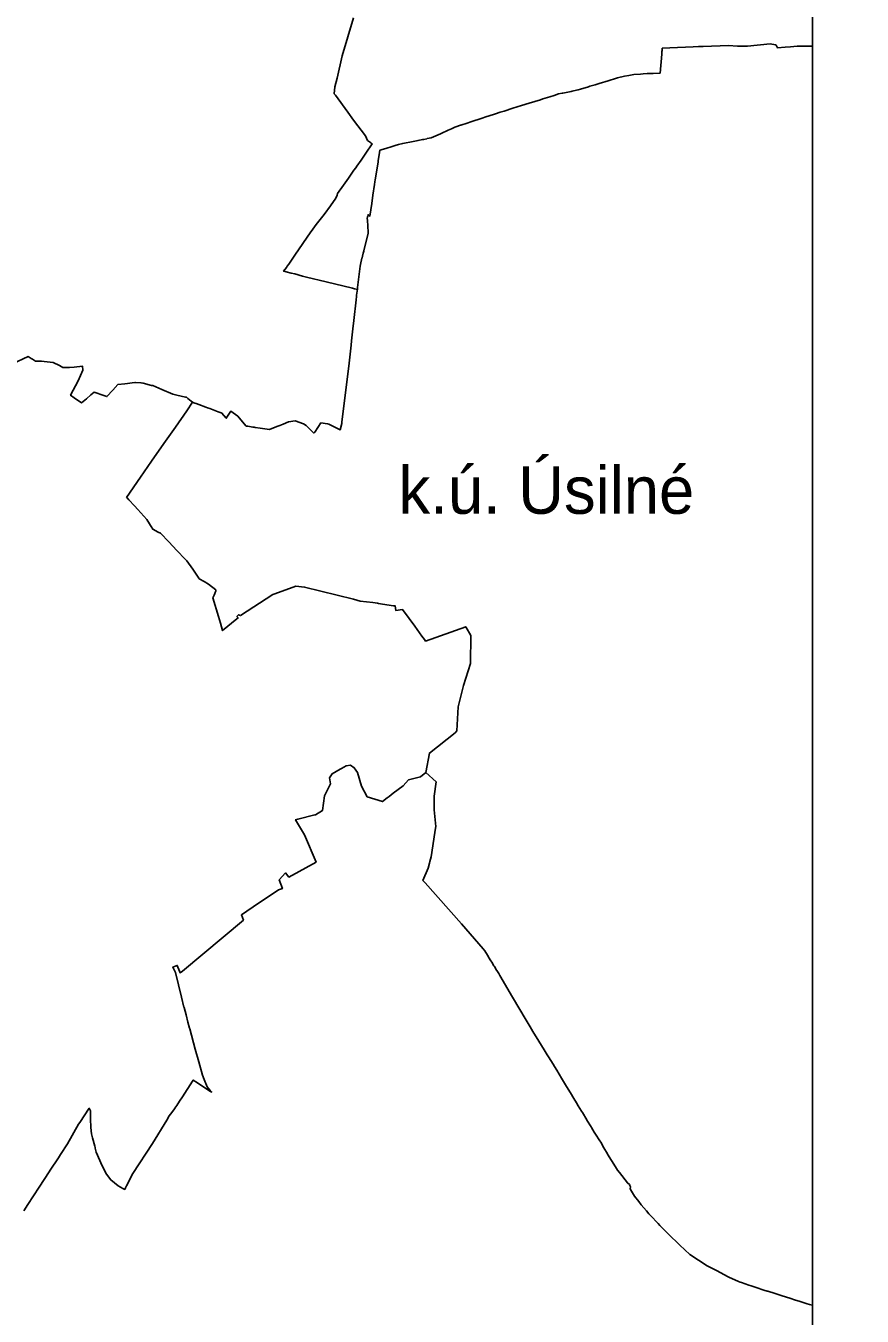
# Model space of a CAD drawing. Extents: x -757891 to -747391, y -1166581 to -1159156.
# Drawn here: x -754302 to -752536, y -1164084 to -1161361 of the extents above; entities that cross this region are included whole.
import ezdxf

# ---------------------------------------------------------------- set-up
doc = ezdxf.new("R2010")
doc.units = 0
for name, color, linetype in [('formát', 7, 'Continuous'), ('Hranice katastrálního území_bez dotčení', 7, 'Continuous'), ('Hranice katastrálního území_dotčené', 7, 'Continuous')]:
    doc.layers.add(name, color=color, linetype=linetype)

msp = doc.modelspace()

# ---------------------------------------------------------------- linework, layer by layer
at = {"layer": 'formát'}
for points in [[(-757891.5, -1159156.4), (-752641.5, -1159156.4), (-752641.5, -1166581.4), (-757891.5, -1166581.4)], [(-752641.5, -1159156.4), (-747391.5, -1159156.4), (-747391.5, -1166581.4), (-752641.5, -1166581.4)]]:
    msp.add_lwpolyline(points, close=True, dxfattribs=at)
at = {"layer": 'Hranice katastrálního území_bez dotčení'}
for points in [[(-753542, -1161619.2), (-753529.1, -1161615.2), (-753522.6, -1161613.2), (-753515.2, -1161611.2), (-753506.6, -1161608.8), (-753484.3, -1161604.5), (-753474.2, -1161602.5), (-753464.5, -1161600.7), (-753462.1, -1161600.2), (-753455.6, -1161598.7), (-753455.2, -1161598.6), (-753446.1, -1161596.6), (-753426.7, -1161588.5), (-753425.5, -1161587.9), (-753410.2, -1161580.9), (-753403.5, -1161577.9), (-753396.3, -1161574.6), (-753394.1, -1161573.9), (-753384.3, -1161570.5), (-753384, -1161570.4), (-753370.5, -1161565.8), (-753362.8, -1161563.3), (-753338.7, -1161555.5), (-753330.8, -1161552.9), (-753314.8, -1161547.7), (-753310.8, -1161546.4), (-753300.6, -1161543.1), (-753292, -1161540.4), (-753274.1, -1161534.6), (-753255.6, -1161528.7), (-753239.3, -1161523.7), (-753215.4, -1161516.4), (-753210.4, -1161514.9), (-753201.1, -1161511.9), (-753195.8, -1161510.2), (-753187.1, -1161507.4), (-753177.3, -1161504.3), (-753169.8, -1161502.8), (-753168.8, -1161502.6), (-753150.8, -1161498.9), (-753148.8, -1161498.5), (-753139.7, -1161496.6), (-753136.2, -1161495.6), (-753135.8, -1161495.4), (-753131.3, -1161494.1), (-753114.5, -1161489), (-753111.8, -1161488.2), (-753100.5, -1161484.8), (-753092, -1161482.2), (-753072.9, -1161476.5), (-753055.4, -1161471.2), (-753053, -1161470.6), (-753038.4, -1161467), (-753029.1, -1161465.4), (-753018.5, -1161463.6), (-753004.8, -1161462.3), (-752998.8, -1161461.8), (-752990.2, -1161461.4), (-752981.6, -1161461.1), (-752979.7, -1161461), (-752977.8, -1161461), (-752963.2, -1161460.4), (-752959.7, -1161420.1), (-752959.2, -1161415.1), (-752959.2, -1161414.7), (-752959, -1161412.5), (-752958.6, -1161408), (-752942.6, -1161407.1), (-752893.5, -1161405), (-752881.8, -1161404.5), (-752872.1, -1161404.2), (-752818.6, -1161402.3), (-752799.9, -1161403.4), (-752778.8, -1161403.5), (-752730.7, -1161398.9), (-752719.6, -1161400.9), (-752718.1, -1161401.1), (-752715.3, -1161406.8), (-752699.4, -1161405.5), (-752688, -1161404.6), (-752673.7, -1161403.5), (-752655.6, -1161403.4), (-752641.5, -1161403.3)], [(-753602.1, -1161917), (-753601.7, -1161913), (-753596.6, -1161867.6), (-753595.9, -1161864.3), (-753592.6, -1161850.7), (-753592.3, -1161849.8), (-753591.6, -1161846.8), (-753589.9, -1161840), (-753588.9, -1161835.9), (-753588.7, -1161835.2), (-753579.6, -1161798.2), (-753579.2, -1161796), (-753580.9, -1161770.5), (-753581.4, -1161767.4), (-753580.6, -1161763.9), (-753580.2, -1161762.3), (-753579.5, -1161759.3), (-753575.8, -1161762.1), (-753571.9, -1161735.4), (-753569.3, -1161717.7), (-753566, -1161695.7), (-753565.4, -1161690.1), (-753564.8, -1161685.6), (-753562.3, -1161673.4), (-753558.5, -1161647.5), (-753558.1, -1161645), (-753556.2, -1161632.9), (-753554.8, -1161623.2), (-753542, -1161619.2)], [(-753129, -1163650.8), (-753135.8, -1163639.4), (-753139.7, -1163633.1), (-753144.9, -1163624.4), (-753152.5, -1163611.9), (-753153.8, -1163609.8), (-753162.7, -1163595), (-753171.2, -1163580.9), (-753181.3, -1163564.3), (-753186.1, -1163556.6), (-753189.2, -1163551.6), (-753198.8, -1163536.1), (-753201.3, -1163532.1), (-753208, -1163521.4), (-753219.2, -1163503.3), (-753232.1, -1163482.5), (-753237.5, -1163473.1), (-753239.8, -1163469.1), (-753245.7, -1163459), (-753274.4, -1163410), (-753301.3, -1163364.9), (-753303.9, -1163360.6), (-753307.7, -1163354.3), (-753308.3, -1163353.2), (-753312.9, -1163345.7), (-753314, -1163344), (-753318.7, -1163336.2), (-753320.3, -1163333.6), (-753325.1, -1163325.7), (-753326.1, -1163324), (-753330.8, -1163316.3), (-753333, -1163312.8), (-753336.8, -1163308.4), (-753354.8, -1163287.4), (-753382.1, -1163255.6), (-753459.3, -1163168.8), (-753461.2, -1163166.6), (-753462.1, -1163165.9), (-753463.8, -1163163.9), (-753452.8, -1163138.1), (-753450, -1163127.2), (-753449.2, -1163124.1), (-753446.5, -1163113.9), (-753445.1, -1163105), (-753437.9, -1163058.1), (-753436.7, -1163050.2), (-753439.9, -1163014.7), (-753440.4, -1162986.2), (-753436.2, -1162955.7), (-753457.6, -1162935.9)], [(-752641.5, -1164060.6), (-752642.2, -1164060.4), (-752648, -1164058.5), (-752652.4, -1164057.2), (-752665.1, -1164053.3), (-752667.4, -1164052.6), (-752679.2, -1164048.9), (-752687.4, -1164046.3), (-752707.6, -1164039.8), (-752720.4, -1164035.8), (-752736, -1164030.9), (-752736.9, -1164030.6), (-752743.9, -1164028.3), (-752760.3, -1164023), (-752771.1, -1164019.5), (-752775.6, -1164018), (-752791.5, -1164012.7), (-752794.4, -1164011.5), (-752797.7, -1164010.1), (-752812, -1164004.2), (-752816.6, -1164001.8), (-752820.8, -1163999.5), (-752842.6, -1163988), (-752849.9, -1163984.1), (-752863.5, -1163976.9), (-752900.2, -1163953.1), (-752921.6, -1163933.9), (-752924.5, -1163931.1), (-752943.3, -1163912.8), (-752957.8, -1163898), (-752963.7, -1163892), (-752967.5, -1163888), (-752983.4, -1163870.9), (-752986.8, -1163867.3), (-752992.1, -1163861.3), (-753003.2, -1163848.5), (-753008.3, -1163841.7), (-753017.4, -1163829.9), (-753023.3, -1163820), (-753026.2, -1163815.1), (-753025.7, -1163810.4), (-753027, -1163807.5), (-753027.9, -1163805.5), (-753032.1, -1163802.1), (-753048.7, -1163780.5), (-753049, -1163780.2), (-753052.9, -1163775.2), (-753057.2, -1163768.5), (-753057.5, -1163768.1), (-753066, -1163755.1), (-753073.9, -1163741.4), (-753074.4, -1163740.6), (-753081.7, -1163727.9), (-753088.3, -1163716.5), (-753090.4, -1163713.3), (-753099.3, -1163699.7), (-753099.4, -1163699.5), (-753102.2, -1163695.1), (-753108, -1163685.6), (-753109, -1163683.8), (-753117.7, -1163669.5), (-753118, -1163669), (-753127.1, -1163653.9), (-753127.3, -1163653.5), (-753129, -1163650.8)]]:
    msp.add_lwpolyline(points, dxfattribs=at)
at = {"layer": 'Hranice katastrálního území_dotčené'}
for points in [[(-753574.6, -1161607), (-753581, -1161602.3), (-753581.8, -1161600.4), (-753582.8, -1161598), (-753583.3, -1161596.7), (-753585.1, -1161593.3), (-753585.4, -1161592.5), (-753610.1, -1161559.7), (-753622.5, -1161542.8), (-753648.7, -1161507.2), (-753651.2, -1161503.8), (-753649.8, -1161489.6), (-753645, -1161471), (-753634.2, -1161423.7), (-753610.1, -1161343.9)], [(-754077.6, -1162113.8), (-754072, -1162113.1), (-754070.5, -1162113.1), (-754059.1, -1162113.6), (-754054.7, -1162114.7), (-754036.5, -1162119.3), (-754034.3, -1162119.8), (-754015.2, -1162128.2), (-753992, -1162137.9), (-753983.4, -1162139.9), (-753965.1, -1162143.9), (-753963.2, -1162144.3), (-753961.4, -1162145.6), (-753960, -1162146.9), (-753953.4, -1162152.3), (-753950.5, -1162154.7), (-753947.3, -1162155.9), (-753945.6, -1162156.5), (-753942.5, -1162157.6), (-753937, -1162159.7), (-753922, -1162165.3), (-753918.8, -1162166.5), (-753913.9, -1162168.4), (-753899.8, -1162173.6), (-753896.3, -1162174.9), (-753889.7, -1162177.4), (-753888.3, -1162177.9), (-753879.2, -1162188.5), (-753869.7, -1162174), (-753854.6, -1162184.5), (-753841, -1162200.3), (-753836.8, -1162205.2), (-753835.7, -1162205.3), (-753833.8, -1162205.6), (-753822.8, -1162207.3), (-753819.9, -1162207.7), (-753818, -1162208), (-753807.7, -1162209.6), (-753787.5, -1162212.6), (-753772, -1162206.4), (-753766.2, -1162204.1), (-753758.7, -1162201.1), (-753747.4, -1162196.5), (-753733.5, -1162194.2), (-753715.8, -1162200.5), (-753710.5, -1162204.3), (-753693.9, -1162220.1), (-753692.3, -1162217.7), (-753679.1, -1162198.2), (-753665.2, -1162200.1), (-753662.6, -1162201.4), (-753638.4, -1162213), (-753635.3, -1162199.9), (-753635.1, -1162198.8), (-753634.8, -1162197.6), (-753634.7, -1162195.9), (-753620, -1162078.5), (-753615.3, -1162034.5), (-753614.3, -1162025.4), (-753611.7, -1162000), (-753609.8, -1161982.3), (-753605.1, -1161938.6), (-753604.4, -1161931.6), (-753604, -1161928.2), (-753603.6, -1161925.7), (-753603.5, -1161925.2), (-753602.6, -1161919.9), (-753602.1, -1161917), (-753608.6, -1161915.5), (-753612.6, -1161914.5), (-753668.4, -1161900.8), (-753709.5, -1161890.8), (-753718, -1161888.5), (-753734.5, -1161884.2), (-753741.7, -1161882.4), (-753752.9, -1161879.5), (-753756.5, -1161878.6), (-753757.9, -1161878.3), (-753752.2, -1161870.4), (-753750.2, -1161867.6), (-753747.2, -1161863.2), (-753734.2, -1161844.4), (-753700.4, -1161795.4), (-753699.8, -1161794.5), (-753696.4, -1161789.7), (-753689.3, -1161779.6), (-753672.5, -1161758.4), (-753659, -1161740.5), (-753647.6, -1161724.1), (-753645.2, -1161717.9), (-753643.9, -1161714.5), (-753631.4, -1161696.6), (-753621, -1161681.7), (-753609.6, -1161665.2), (-753605.8, -1161660.3), (-753603.5, -1161657), (-753594.2, -1161644), (-753584.2, -1161629.4), (-753570.7, -1161609.8), (-753573.2, -1161608), (-753574.6, -1161607)], [(-754330, -1162073.9), (-754297.1, -1162058.7), (-754290.9, -1162062.4), (-754288.1, -1162064.1), (-754281.7, -1162067.9), (-754269.3, -1162067.9), (-754263.3, -1162068.6), (-754244.3, -1162070.8), (-754231.3, -1162077.7), (-754223.8, -1162081.7), (-754209.8, -1162081.4), (-754200, -1162080.6), (-754182.2, -1162079), (-754181.5, -1162087.2), (-754191.9, -1162109.9), (-754207.8, -1162140.2), (-754199.9, -1162145.5), (-754184.5, -1162155.9), (-754174.4, -1162147.4), (-754164.8, -1162139.5), (-754157.8, -1162133.9), (-754137.7, -1162140.6), (-754130.8, -1162142.9), (-754118.2, -1162129.1), (-754107.7, -1162117.6), (-754092.9, -1162115.7), (-754087.6, -1162115.1), (-754077.6, -1162113.8)], [(-754157.8, -1162133.9), (-754164.8, -1162139.5), (-754174.4, -1162147.4), (-754184.5, -1162155.9), (-754199.9, -1162145.5), (-754207.8, -1162140.2), (-754191.9, -1162109.9), (-754181.5, -1162087.2), (-754182.2, -1162079), (-754200, -1162080.6), (-754209.8, -1162081.4), (-754223.8, -1162081.7), (-754231.3, -1162077.7), (-754244.3, -1162070.8), (-754263.3, -1162068.6), (-754269.3, -1162067.9), (-754281.7, -1162067.9), (-754288.1, -1162064.1), (-754290.9, -1162062.4), (-754297.1, -1162058.7), (-754330, -1162073.9)], [(-753581.3, -1162987.6), (-753549.5, -1162997.4), (-753539.6, -1162989.8), (-753535.3, -1162986.5), (-753526.8, -1162979.9), (-753505.9, -1162964.1), (-753494.4, -1162951.8), (-753469.3, -1162945.4), (-753457.6, -1162935.9), (-753450.3, -1162895.2), (-753395.5, -1162852.4), (-753392, -1162848.4), (-753389.3, -1162797.9), (-753378.4, -1162752.7), (-753363.6, -1162705.9), (-753363, -1162647.2), (-753373.4, -1162628.7), (-753458.3, -1162658.8), (-753460.8, -1162655.4), (-753465.9, -1162648.4), (-753480.9, -1162627.7), (-753504.7, -1162595), (-753505.4, -1162594), (-753506.7, -1162592.3), (-753521, -1162594.4), (-753522.2, -1162584.8), (-753525.9, -1162584.2), (-753548.9, -1162580.7), (-753557.8, -1162579.3), (-753559.8, -1162579), (-753569.3, -1162577.8), (-753596.3, -1162574.6), (-753610.4, -1162570.7), (-753713.6, -1162545), (-753732.2, -1162543.2), (-753745.5, -1162547.9), (-753778.8, -1162559.7), (-753780.8, -1162560.9), (-753848.8, -1162605), (-753853.4, -1162603.3), (-753856.4, -1162606.9), (-753854.2, -1162610), (-753856.5, -1162611.9), (-753886.8, -1162636.9), (-753891.1, -1162621.3), (-753895.3, -1162606.9), (-753907.3, -1162567.9), (-753904.7, -1162561.7), (-753903.3, -1162558.4), (-753900.9, -1162553.2), (-753901.2, -1162550.9), (-753916.2, -1162538.8), (-753925.6, -1162533.4), (-753926, -1162533.1), (-753936.1, -1162527.3), (-753936.8, -1162526.2), (-753949.7, -1162507.4), (-753962, -1162489.5), (-753965.6, -1162485.8), (-753983.2, -1162467.4), (-754000.4, -1162449.3), (-754018, -1162431.1), (-754022.5, -1162428.8), (-754034.1, -1162422.8), (-754037.7, -1162416.9), (-754038.8, -1162415.2), (-754041.1, -1162411.4), (-754046.6, -1162402.5), (-754065.8, -1162381.5), (-754072.9, -1162373.8), (-754084.6, -1162361), (-754088.5, -1162356.7), (-754089.6, -1162355.6), (-754060.1, -1162313.3), (-754037, -1162278.9), (-754010.5, -1162242), (-753986.4, -1162207.8), (-753962.2, -1162172.9), (-753950.5, -1162154.7), (-753953.4, -1162152.3), (-753960, -1162146.9), (-753961.4, -1162145.6), (-753963.2, -1162144.3), (-753965.1, -1162143.9), (-753983.4, -1162139.9), (-753992, -1162137.9), (-754015.2, -1162128.2), (-754034.3, -1162119.8), (-754036.5, -1162119.3), (-754054.7, -1162114.7), (-754059.1, -1162113.6), (-754070.5, -1162113.1), (-754072, -1162113.1), (-754077.6, -1162113.8), (-754087.6, -1162115.1), (-754092.9, -1162115.7), (-754107.7, -1162117.6), (-754118.2, -1162129.1), (-754130.8, -1162142.9), (-754137.7, -1162140.6), (-754157.8, -1162133.9)], [(-754306.6, -1163861), (-754298, -1163847.8), (-754274.2, -1163811.1), (-754253.1, -1163779), (-754250.8, -1163775.5), (-754233.4, -1163749), (-754228.9, -1163742.1), (-754214.2, -1163719.7), (-754190.9, -1163678.4), (-754188.4, -1163674.7), (-754168.2, -1163644.6), (-754165.3, -1163650), (-754165.9, -1163667.2), (-754164.6, -1163685.3), (-754163.2, -1163698.8), (-754161.1, -1163707.3), (-754156.8, -1163724.8), (-754156, -1163727.8), (-754155.6, -1163729.2), (-754153.5, -1163737.5), (-754141, -1163766.4), (-754132, -1163783.7), (-754122.8, -1163796.1), (-754107.5, -1163808.7), (-754097.7, -1163813.7), (-754093.4, -1163815.9), (-754091.6, -1163812.5), (-754089.4, -1163808.3), (-754076.1, -1163782.5), (-754034.6, -1163719.4), (-754004.3, -1163669.8), (-753999.3, -1163661), (-753996.8, -1163657.5), (-753996.6, -1163657.2), (-753987.9, -1163644.9), (-753987.5, -1163644.3), (-753983.7, -1163639.1), (-753977.4, -1163630), (-753971.2, -1163620.4), (-753950.2, -1163587.9), (-753948.8, -1163585.4), (-753939.8, -1163591), (-753913.4, -1163608.4), (-753909.5, -1163610.6), (-753913.3, -1163607.1), (-753919.5, -1163599.5), (-753926, -1163583.8), (-753929.1, -1163574.6), (-753937, -1163546.5), (-753944.4, -1163519.8), (-753956.1, -1163477.2), (-753956.5, -1163475.8), (-753959.8, -1163463.2), (-753964, -1163447.8), (-753968.1, -1163432.1), (-753968.3, -1163431.2), (-753973.4, -1163410.4), (-753986.2, -1163358.2), (-753992, -1163347), (-753984.9, -1163344.2), (-753982.6, -1163343.4), (-753977.4, -1163355.3), (-753976.6, -1163358.9), (-753971.1, -1163355.1), (-753842.9, -1163247.7), (-753847.2, -1163236.7), (-753810.8, -1163212.2), (-753807.1, -1163209.6), (-753768.7, -1163183.8), (-753766.8, -1163183.2), (-753762.1, -1163181.8), (-753760.6, -1163181.3), (-753767.3, -1163162.6), (-753754.1, -1163148.2), (-753746.7, -1163156.8), (-753689.3, -1163125.4), (-753714.2, -1163067.8), (-753732.8, -1163035.8), (-753728, -1163034.7), (-753692.1, -1163025.8), (-753690.4, -1163025.4), (-753676.1, -1163016.5), (-753671.5, -1162985.4), (-753658.7, -1162959.9), (-753661, -1162947.3), (-753655.4, -1162938.7), (-753638.7, -1162929.4), (-753635.9, -1162927.7), (-753626.2, -1162921.8), (-753616.9, -1162920.9), (-753608.7, -1162926.3), (-753602.2, -1162936.3), (-753593.6, -1162964.7), (-753581.3, -1162987.6)]]:
    msp.add_lwpolyline(points, dxfattribs=at)

# ---------------------------------------------------------------- texts
at = {"layer": 'Hranice katastrálního území_bez dotčení'}
msp.add_text('k.ú. Úsilné', height=100, dxfattribs=at).set_placement((-753515.3, -1162390.3))

doc.saveas('drawing.dxf')
